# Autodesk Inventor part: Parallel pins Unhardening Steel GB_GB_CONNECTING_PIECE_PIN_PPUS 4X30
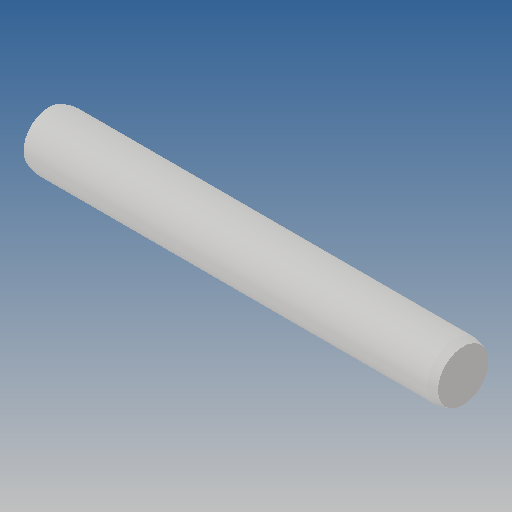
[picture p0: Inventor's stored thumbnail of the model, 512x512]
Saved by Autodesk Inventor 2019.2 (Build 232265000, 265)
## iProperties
Created: 2013-09
Part Number: Parallel pins Unhardening Steel GB_GB_CONNECTING_PIECE_PIN_PPUS 4X30
Material: Ogólny
Document SubType Name: Modeling
Designer: CADENGINEERING4
Density: 1 g/cm^3
Appearance: Domyślna
Author: CADENGINEERING4
Revision Number: ÈÎºÎ
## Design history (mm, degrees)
feature "Base-Revolve"
node "Bryła1"
